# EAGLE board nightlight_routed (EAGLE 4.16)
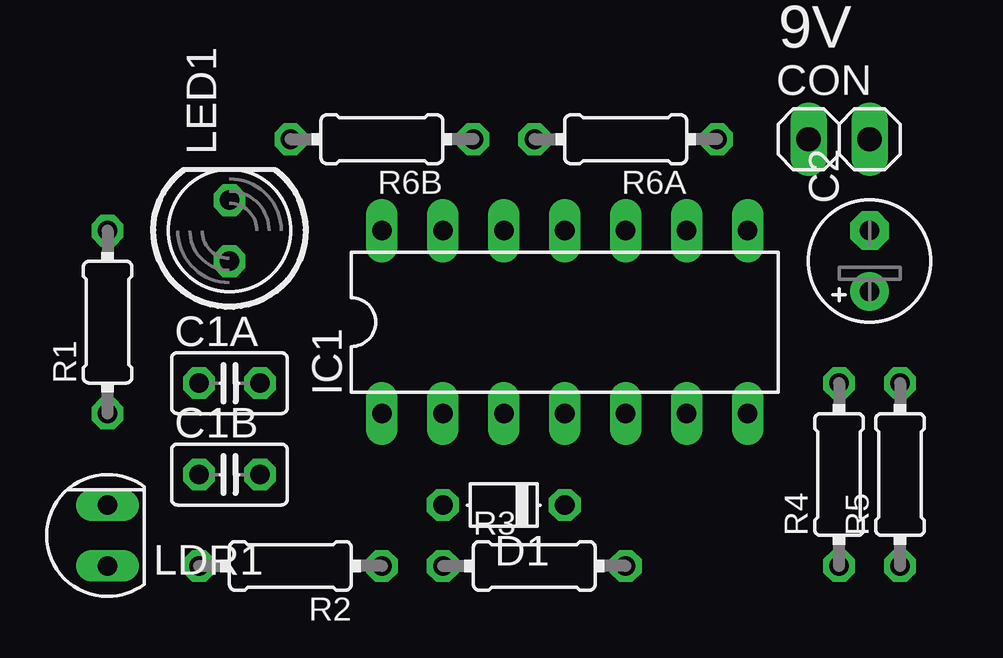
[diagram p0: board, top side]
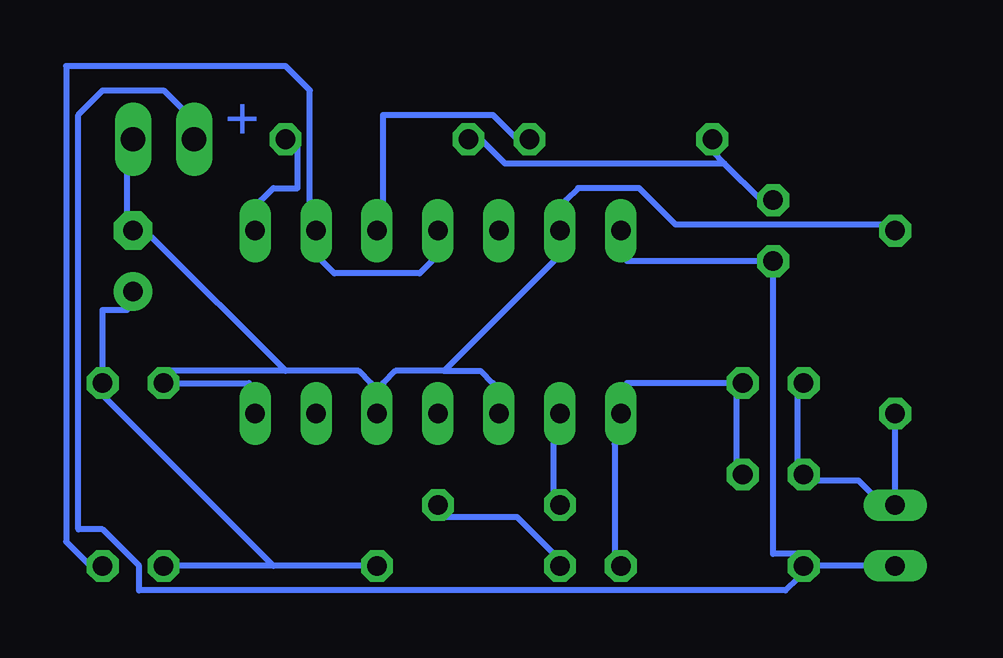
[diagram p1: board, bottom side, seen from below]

No outline drawn. Coordinates in mm, seen from the top.
Copper layers (1*16): Top 0.035mm / dielectric 1.5mm / Bottom 0.035mm
Design rules "default": minimum track width 10mil, minimum drill 24mil, track to track 8mil, track to pad 8mil, pad to pad 8mil, via to via 8mil, smd to smd 8mil, copper to edge 40mil, drill to drill 8mil, minimum pad ring 10mil, minimum via ring 8mil, stop-mask expansion 4mil, vias tented up to drill 0mil, thermal gap 10mil

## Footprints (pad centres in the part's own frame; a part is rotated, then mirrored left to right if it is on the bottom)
C025-025X050 = drill 0.813 octagon: 1 -1.27,0; 2 1.27,0
E2,5-5 = drill 0.813 pad 1.6 round: + -1.27,0 | drill 0.813 pad 1.6 octagon: - 1.27,0
1X02 = drill 1.016 long: 1 -1.27,0; 2 1.27,0
D-5 = drill 0.813 octagon: A 2.54,0; C -2.54,0
DIL14 = drill 0.813 long: 1 -7.62,-3.81; 2 -5.08,-3.81; 3 -2.54,-3.81; 4 0,-3.81; 5 2.54,-3.81; 6 5.08,-3.81; 7 7.62,-3.81; 8 7.62,3.81; 9 5.08,3.81; 10 2.54,3.81; 11 0,3.81; 12 -2.54,3.81; 13 -5.08,3.81; 14 -7.62,3.81
SFH206 = drill 0.813 long: A 0,-1.27; K 0,1.27
LED5MM = drill 0.813 octagon: A -1.27,0; K 1.27,0
0204/7 = drill 0.813 octagon: 1 -3.81,0; 2 3.81,0

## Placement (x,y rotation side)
C1A  0.1u  [C025-025X050]  10.16,10.16 0 top
C1B  0.1u  [C025-025X050]  10.16,6.35 0 top
C2  1u  [E2,5-5]  36.83,15.24 90 top
CON  [1X02]  35.56,20.32 0 top
D1  1N4002  [D-5]  21.59,5.08 180 top
IC1  MC14106BCP  [DIL14]  24.13,12.7 0 top
LDR1  [SFH206]  5.08,3.81 0 top
LED1  [LED5MM]  10.16,16.51 90 top
R1  50k  [0204/7]  5.08,12.7 90 top
R2  2M  [0204/7]  12.7,2.54 180 top
R3  1.5k  [0204/7]  22.86,2.54 0 top
R4  50M  [0204/7]  35.56,6.35 90 top
R5  30k  [0204/7]  38.1,6.35 90 top
R6A  1k  [0204/7]  26.67,20.32 180 top
R6B  1k  [0204/7]  16.51,20.32 180 top

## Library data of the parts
C1A C1B C2 R1-R5 R6A R6B = rcl
CON = pinhead
D1 = diode
IC1 = 74xx-eu
LDR1 = opto-trans-siemens
LED1 = led

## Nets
S$1: CON.1 IC1.14 LDR1.A LED1.A R2.2
S$3: C1A.1 C1B.1 LDR1.K R1.1
S$4: C1A.2 C1B.2 IC1.1 R2.1
S$5: D1.A IC1.2
S$6: D1.C R3.1
S$7: C2.+ R3.2 R4.1 R5.2
S$8: C2.- CON.2 IC1.3 IC1.5 IC1.7 IC1.13 R1.2 R4.2
S$9: IC1.9 IC1.11 R5.1
S$10: IC1.10 R6B.1
S$11: IC1.8 R6A.1
S$12: LED1.K R6A.2 R6B.2

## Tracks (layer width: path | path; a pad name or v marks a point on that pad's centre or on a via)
S$1
  Bottom 0.254: IC1.14 16.26,15.24 LED1.A 10.16,3.05 9.14,3.05 R2.2 | LDR1.A R2.2 | CON.1 34.54,21.34 35.56,22.35 38.1,22.35 39.12,21.34 39.12,4.06 38.1,4.06 36.58,2.54 36.58,1.52 9.65,1.52 9.14,2.03 R2.2
S$3
  Bottom 0.254: R1.1 LDR1.K 6.1,5.59 6.6,6.1 8.64,6.1 C1B.1 9.14,6.6 9.14,9.65 C1A.1
S$4
  Bottom 0.254: C1B.2 11.68,6.6 11.68,9.65 C1A.2 16.26,10.16 IC1.1 16.76,7.62 16.76,3.05 R2.1
S$5
  Bottom 0.254: D1.A 19.3,5.59 19.3,7.62 IC1.2
S$6
  Bottom 0.254: R3.1 19.3,3.05 20.83,4.57 23.88,4.57 D1.C
S$7
  Bottom 0.254: C2.+ 37.08,13.21 38.1,13.21 R5.2 38.1,9.65 30.99,2.54 | R3.2 30.99,2.54 | 30.99,2.54 R4.1
S$8
  Bottom 0.254: R1.2 5.59,16.76 14.22,16.76 15.75,18.29 18.29,18.29 18.8,17.78 IC1.13 19.3,15.24 23.88,10.67 | CON.2 37.08,19.3 37.08,17.27 C2.- 36.07,16.26 30.48,10.67 | 23.88,10.67 25.91,10.67 26.42,10.16 IC1.5 26.92,10.16 27.43,10.67 30.48,10.67 | 23.88,10.67 22.35,10.67 21.84,10.16 IC1.3 | IC1.7 32,10.16 R4.2 35.56,10.67 30.48,10.67
S$9
  Bottom 0.254: IC1.11 24.38,15.24 24.89,14.73 28.45,14.73 28.96,15.24 IC1.9 29.46,17.78 29.46,22.35 30.48,23.37 39.62,23.37 39.62,3.56 38.61,2.54 R5.1
S$10
  Bottom 0.254: IC1.10 26.42,17.78 26.42,21.34 21.84,21.34 20.83,20.32 R6B.1
S$11
  Bottom 0.254: R6A.1 29.97,20.32 29.97,18.29 30.99,18.29 31.5,17.78 IC1.8
S$12
  Bottom 0.254: 12.19,19.3 12.7,19.81 R6B.2 | 12.19,19.3 10.67,17.78 LED1.K | 12.19,19.3 21.34,19.3 22.35,20.32 R6A.2

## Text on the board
Bottom: +
tNames: 9V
